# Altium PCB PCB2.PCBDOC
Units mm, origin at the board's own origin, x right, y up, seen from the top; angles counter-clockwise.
Board outline 130.05 x 89.41 mm, 2 copper layers (Top Layer, Bottom Layer); 28 components, 33 nets, 131 pads, 11 vias.
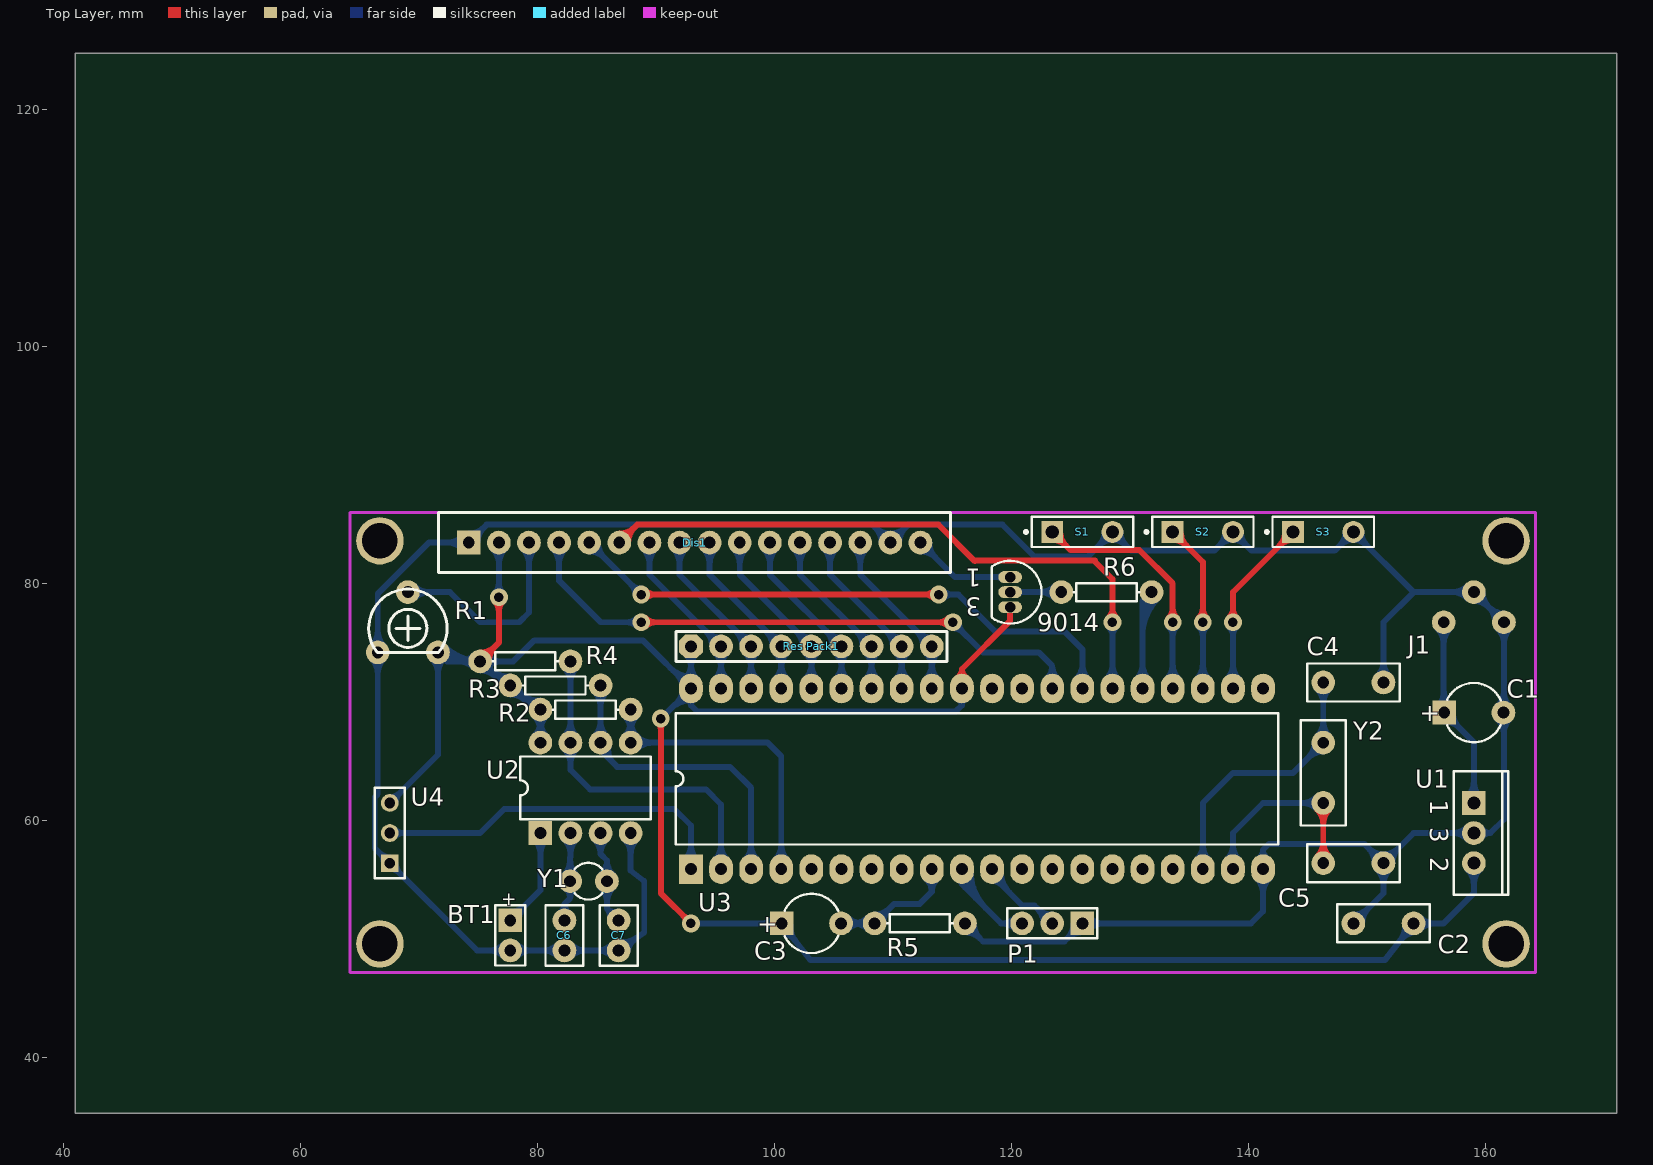
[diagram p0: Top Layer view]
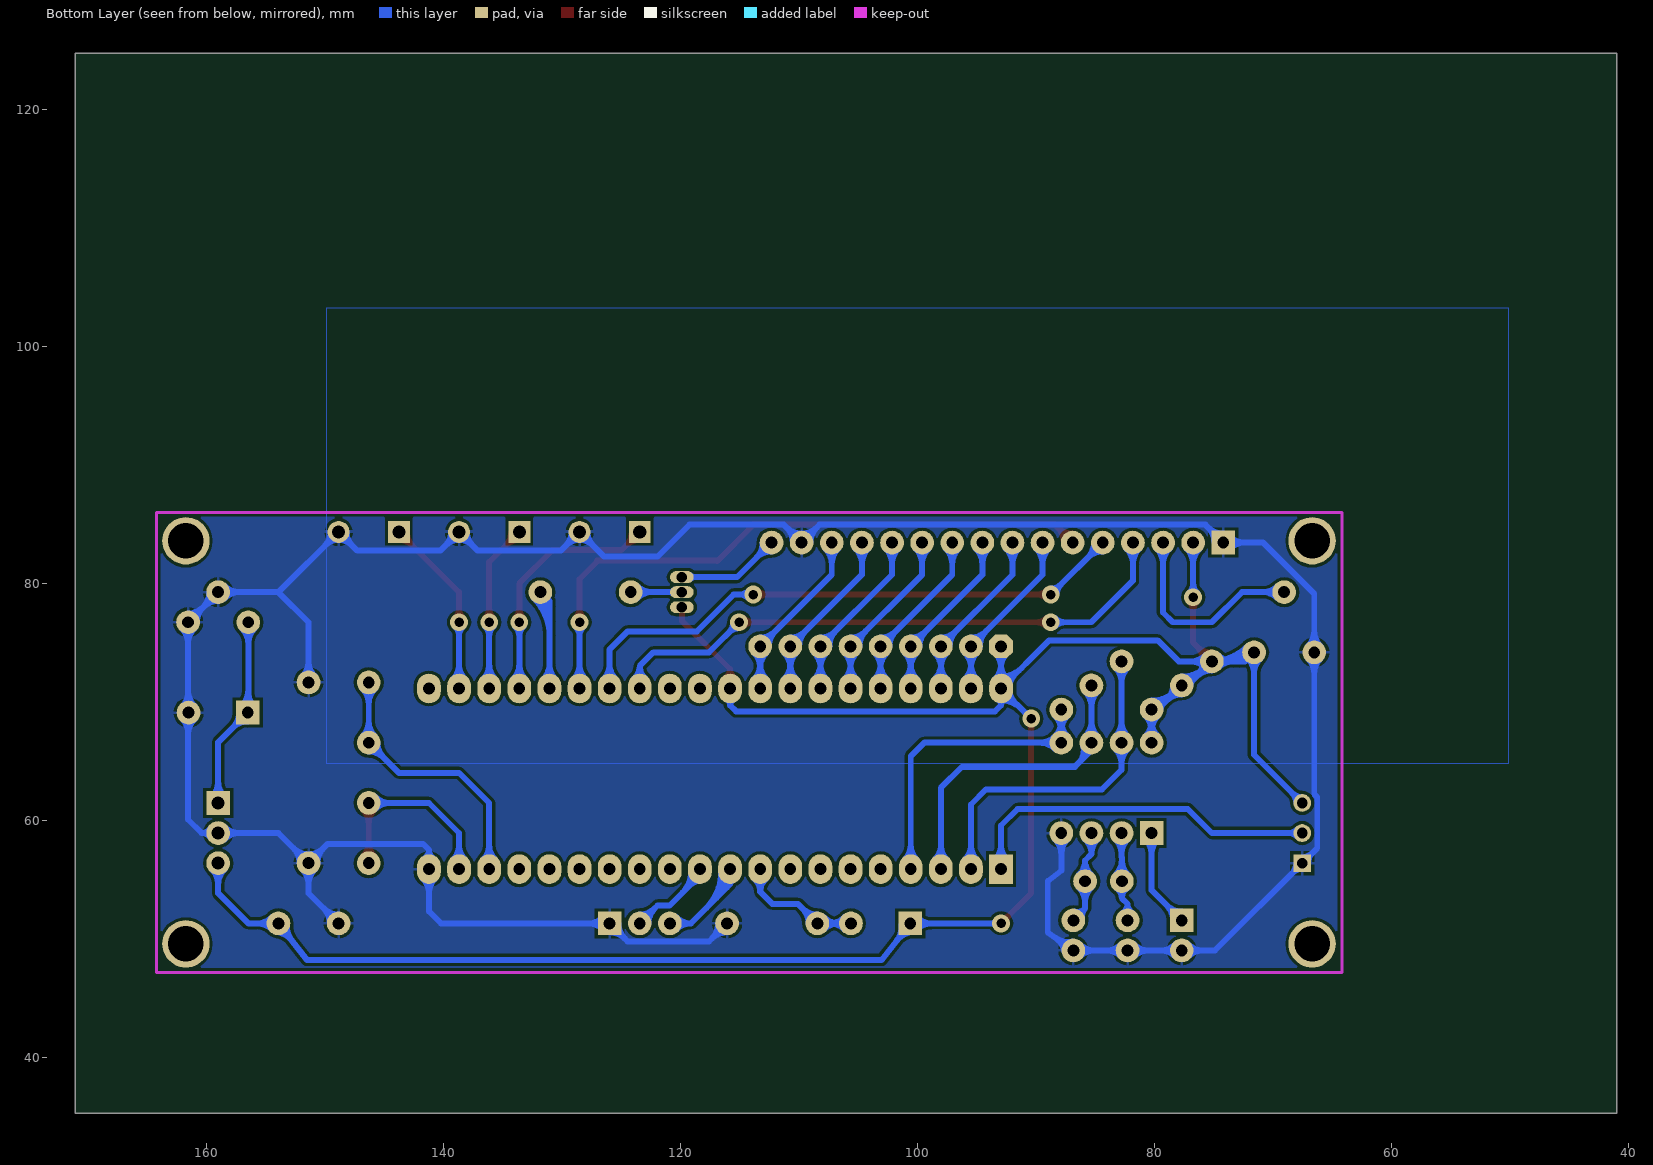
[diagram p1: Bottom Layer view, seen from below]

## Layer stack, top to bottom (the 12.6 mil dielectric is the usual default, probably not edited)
Top Layer: signal copper 0.0356
Dielectric: dielectric 0.32, FR-4, Dk 4.8
Bottom Layer: signal copper 0.0356

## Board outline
41.021,123.063 41.021,35.306 171.069,35.306 171.069,124.714 41.021,124.714

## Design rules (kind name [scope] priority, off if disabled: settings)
Clearance [All] p1: gap=0.254
ComponentClearance [All] p1: gap=0.254 collisioncheckmode=0
PolygonConnect [All] p1: connectstyle=Relief reliefconductorwidth=0.254 reliefentries=4 polygonreliefangle="90 Angle"
RoutingVias [All] p1: holewidth=0.711 width=1.27 viastyle="Through Hole" minholewidth=0.711 minwidth=1.27 maxholewidth=0.711 maxwidth=1.27
SolderMaskExpansion [All] p1: expansion=0.102
TestPointUsage [All] p1: valid=0 allowmultiple=FALSE
Testpoint [All] p1: side=15 testpointundercomponent=TRUE minsize=1.016 maxsize=2.54 preferedsize=1.524 minholesize=0 maxholesize=1.016 preferedholesize=0.813 testpointgrid=0.025 style=1023 order=1234567890
Width [All] p1: maxlimit=0.5 minlimit=0.254 preferedwidth=0.254 toplayer_minwidth=0.5 toplayer_prefwidth=0.5 bottomlayer_minwidth=0.5 bottomlayer_prefwidth=0.5 minimp=50.000000 maximp=50.000000 favimp=50.000000
17 further rules are at their usual default settings.

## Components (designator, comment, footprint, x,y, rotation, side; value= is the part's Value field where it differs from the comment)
9014 "NPN" BCY-W3 119.888,79.248 r180 top (schematic designator Q1)
BT1 "Battery" BAT-2 77.724,50.292 r270 top
C1 "Cap Pol1" CAPPR5-5x5 159.004,69.088 r0 top
C2 "Cap" CAPR5.08-7.8x3.2 151.384,51.308 r0 top
C3 "Cap Pol1" CAPPR5-5x5 103.124,51.308 r0 top
C4 "Cap" CAPR5.08-7.8x3.2 148.844,71.628 r180 top
C5 "Cap" CAPR5.08-7.8x3.2 148.844,56.388 r180 top
C6 "Cap" CAPR2.54-5.1x3.2 82.296,50.292 r90 top
C7 "Cap" CAPR2.54-5.1x3.2 86.868,50.292 r90 top
Dis1 "LCD1602 BIG" 1602 74.224,83.428 r0 top locked
J1 "电源插头" "电源插头 小" 156.464,76.708 r90 top
P1 "Header 3" HDR1X3#1 125.984,51.308 r180 top
R1 "RPot" 蓝白可调 69.088,79.248 r0 top
R2 "Res1" AXIAL-0.3 84.074,69.342 r180 top
R3 "Res1" AXIAL-0.3 81.534,71.374 r180 top
R4 "Res1" AXIAL-0.3 78.994,73.406 r180 top
R5 "Res1" AXIAL-0.3 112.268,51.308 r180 top
R6 "Res1" AXIAL-0.3 128.016,79.248 r180 top
"Res Pack1" "RES Pack" "Res Pack" 92.964,74.676 r90 top locked
S1 "SW-PB" SPST-2 125.984,84.328 r0 top
S2 "SW-PB" SPST-2 136.144,84.328 r0 top
S3 "SW-PB" SPST-2 146.304,84.328 r0 top
U1 "L7805AB-V" TO220ABN 159.004,58.928 r270 top
U2 "DS1302" DIP8 84.074,62.738 r0 top
U3 "STC89C51" DIP40 92.964,55.88 r90 top
U4 "DS18b20" HDR1X3#2 67.564,56.388 r90 top
Y1 "XTAL" BCY-W2/D3.1 84.328,54.864 r270 top
Y2 "XTAL" RAD-0.2 146.304,64.008 r270 top

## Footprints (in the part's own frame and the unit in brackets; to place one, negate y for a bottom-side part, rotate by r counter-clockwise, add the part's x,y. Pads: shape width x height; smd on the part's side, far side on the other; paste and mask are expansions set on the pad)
1602 [mm]
  rect 2x2 hole 1: 1(0,0)
  round 2 hole 1: 2(2.54,0) 3(5.08,0) 4(7.62,0) 5(10.16,0) 6(12.7,0) 7(15.24,0) 8(17.78,0) 9(20.32,0) 10(22.86,0) 11(25.4,0) 12(27.94,0) 13(30.48,0) 14(33.02,0) 15(35.56,0) 16(38.1,0)
  silkscreen extent -2.54,-2.54 40.64,2.54
AXIAL-0.3 [mm] "Resistor; 2 Leads"
  round 2 hole 1: 1(-3.81,0) 2(3.81,0)
  silkscreen extent -2.77,-0.76 2.77,0.76
BAT-2 [mm] "Multicell Battery; 2 Leads"
  rect 2x2 hole 1: 1(-1.27,0)
  round 2 hole 1: 2(1.27,0)
  silkscreen extent -2.54,-1.27 2.54,1.27
BCY-W2/D3.1 [mm] "Crystal, Thru-Hole; 2 Leads; Body 3.1 x 8.2 mm (Dia.xH)"
  round 2 hole 1: 1(0,1.55) 2(0,-1.55)
  silkscreen extent -1.55,-1.19 1.55,1.17
BCY-W3 [mm] "TO, Flat Index; 3 In-Line, Axial Leads; Body Dia. 4.8mm"
  oval 2x1 hole 0.9: 1(0,-1.27) 2(0,0) 3(0,1.27)
  silkscreen extent -2.65,-2.65 1.55,2.65
CAPPR5-5x5 [mm] "Capacitor, Electrolytic, Radial; Body 5 x 5 mm (Dia.xH typ); Pin Spacing 5 mm (typ)"
  rect 2x2 hole 1: 1(-2.5,0)
  round 2 hole 1: 2(2.5,0)
  silkscreen extent -2.26,-2.5 2.27,2.5
CAPR2.54-5.1x3.2 [mm] "Capacitor, Ceramic, Thru-Hole, Dipped Radial; Body 5.1 x 3.2 mm (WxT) Pin Spacing 2.54 mm (typ)"
  round 2 hole 1: 1(-1.27,0) 2(1.27,0)
  silkscreen extent -2.55,-1.6 2.55,1.6
CAPR5.08-7.8x3.2 [mm] "Capacitor, Ceramic, Thru-Hole, Dipped Radial; Body 7.8 x 3.2 mm (WxT) Pin Spacing 5.08 mm (typ)"
  round 2 hole 1: 1(-2.54,0) 2(2.54,0)
  silkscreen extent -3.9,-1.6 3.9,1.6
DIP8 [mm] "DIP; 8 Leads; Row Spacing 7.62 mm; Pitch 2.54 mm"
  rect 2x2 hole 1: 1(-3.81,-3.81)
  round 2 hole 1: 2(-1.27,-3.81) 3(1.27,-3.81) 4(3.81,-3.81) 5(3.81,3.81) 6(1.27,3.81) 7(-1.27,3.81) 8(-3.81,3.81)
  silkscreen extent -5.5,-2.65 5.5,2.65
DIP40 [mm]
  rect 2.5x2 hole 1: 1(0,0)
  oval 2.5x2 hole 1: 2(0,-2.54) 3(0,-5.08) 4(0,-7.62) 5(0,-10.16) 6(0,-12.7) 7(0,-15.24) 8(0,-17.78) 9(0,-20.32) 10(0,-22.86) 11(0,-25.4) 12(0,-27.94) 13(0,-30.48) 14(0,-33.02) 15(0,-35.56) 16(0,-38.1) 17(0,-40.64) 18(0,-43.18) 19(0,-45.72) 20(0,-48.26) 21(15.24,-48.26) 22(15.24,-45.72) 23(15.24,-43.18) 24(15.24,-40.64) 25(15.24,-38.1) 26(15.24,-35.56) 27(15.24,-33.02) 28(15.24,-30.48) 29(15.24,-27.94) 30(15.24,-25.4) 31(15.24,-22.86) 32(15.24,-20.32) 33(15.24,-17.78) 34(15.24,-15.24) 35(15.24,-12.7) 36(15.24,-10.16) 37(15.24,-7.62) 38(15.24,-5.08) 39(15.24,-2.54) 40(15.24,0)
  silkscreen extent 2.08,-49.53 13.16,1.27
HDR1X3#1 [mm] "Connector; Header; 3 Position"
  rect 2x2 hole 1: 1(0,0)
  round 2 hole 1: 2(2.54,0) 3(5.08,0)
  silkscreen extent -1.27,-1.27 6.35,1.27
HDR1X3#2 [mm] "Connector; Header; 3 Position"
  rect 1.5x1.5 hole 0.9: 1(0,0)
  round 1.5 hole 0.9: 2(2.54,0) 3(5.08,0)
  silkscreen extent -1.27,-1.27 6.35,1.27
RAD-0.2 [mm] "Jumper Wire; 2 Leads"
  round 2 hole 1: 1(-2.54,0) 2(2.54,0)
  silkscreen extent -4.44,-1.91 4.44,1.91
"Res Pack" [mm]
  oct 2x2 hole 1: 1(0,0)
  round 2 hole 1: 2(0,-2.54) 3(0,-5.08) 4(0,-7.62) 5(0,-10.16) 6(0,-12.7) 7(0,-15.24) 8(0,-17.78) 9(0,-20.32)
  silkscreen extent -1.27,-21.59 1.27,1.27
SPST-2 [mm] "Circuit Breaker; 2 Leads"
  rect 1.85x1.85 hole 1.1: 1(-2.54,0)
  round 1.85 hole 1.1: 2(2.54,0)
  silkscreen extent -4.89,-1.27 4.28,1.27
TO220ABN [mm] "TO, Thru-Hole, Vertical, Heatsink Mounted; 3 In-Line Leads; Pitch 2.54 mm; Pin sequence 1, 3, 2"
  rect 2x2 hole 1.1: 1(-2.54,0)
  round 2 hole 1.1: 2(2.54,0) 3(0,0)
  silkscreen extent -5.2,-1.7 5.2,2.9
"电源插头 小" [mm]
  round 2 hole 1: 1(0,0) 2(0,-5.08) 3(2.54,-2.54)
蓝白可调 [mm]
  round 2 hole 1: 1(0,0) 2(-2.54,-5.08) 3(2.54,-5.08)
  silkscreen extent -3.3,-5.11 3.3,0.25

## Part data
9014: "NPN Bipolar Transistor"
BT1: "Multicell Battery"
C1 C3: "Polarized Capacitor (Radial)"
C2 C4 C5 C6 C7: "Capacitor"
P1: "Header, 3-Pin"
R1: "Potentiometer"
R2 R3 R4 R5 R6: "Resistor"
S1 S2 S3: "Switch"
U1: "Precision 1A Regulator"
Y1 Y2: "Crystal Oscillator"

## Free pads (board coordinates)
  round 4 hole 3: 0(66.724,83.579) 1(66.724,49.579) 1(161.724,83.579) 2(161.724,49.579)

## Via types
v1: diameter 1.5, hole 0.8, Top Layer to Bottom Layer, 11 vias

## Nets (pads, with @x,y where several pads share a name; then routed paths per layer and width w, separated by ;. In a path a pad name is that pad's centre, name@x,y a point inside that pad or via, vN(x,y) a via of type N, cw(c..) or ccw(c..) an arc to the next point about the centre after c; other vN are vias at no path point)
GND: BT1.2 C1.2 C2.1 C4.1 C5.1 C6.1 C7.1 Dis1.1 Dis1.15 J1.2 J1.3 P1.1 R1.2 R5.1 S1.2 S2.2 S3.2 U1.3 U2.4 U3.20 U4.1 | length 355.1
  Bottom Layer w0.5: R1.2@66.018,73.638 cw(c64.737,72.357) 66.548,72.357 cw(c68.359,72.357) R1.2@67.078,73.638 ; R1.2@66.018,74.698 ccw(c64.737,75.979) 66.548,75.979 ccw(c68.359,75.979) R1.2@67.078,74.698 ; U4.1@67.064,56.388 ccw(c65.857,56.388) 66.71,57.242 ccw(c67.564,58.095) U4.1@67.564,56.888 ; U4.1@67.564,55.888 cw(c67.564,54.681) 68.418,55.534 cw(c69.271,56.388) U4.1@68.064,56.388 ; Dis1.1@73.694,82.898 ccw(c72.413,81.617) 72.413,83.428 ccw(c72.413,85.239) Dis1.1@73.694,83.958 ; Dis1.1@74.224,84.178 ccw(c74.224,85.989) 75.504,84.708 ccw(c76.785,83.428) Dis1.1@74.974,83.428 ; BT1.2@77.194,48.492 ccw(c75.913,47.211) 75.913,49.022 ccw(c75.913,50.833) BT1.2@77.194,49.552 ; BT1.2@78.254,48.492 cw(c79.535,47.211) 79.535,49.022 cw(c79.535,50.833) BT1.2@78.254,49.552 ; C6.1@81.766,48.492 ccw(c80.485,47.211) 80.485,49.022 ccw(c80.485,50.833) C6.1@81.766,49.552 ; C6.1@82.826,48.492 cw(c84.107,47.211) 84.107,49.022 cw(c84.107,50.833) C6.1@82.826,49.552 ; C7.1@86.338,48.492 ccw(c85.057,47.211) 85.057,49.022 ccw(c85.057,50.833) C7.1@86.338,49.552 ; C7.1@86.995,49.761 ccw(c87.303,51.545) 88.347,50.066 ccw(c89.391,48.587) C7.1@87.607,48.895 ; U2.4@87.354,58.398 cw(c86.073,57.117) 87.884,57.117 cw(c89.695,57.117) U2.4@88.414,58.398 ; U2.4 87.884,55.753 89.027,54.864 89.027,50.546 C7.1 C6.1 BT1.2 74.93,49.022 U4.1 66.294,57.658 66.294,61.951 66.548,62.205 66.548,79.121 70.855,83.428 Dis1.1 75.734,84.938 108.274,84.938 Dis1.15 111.294,84.938 119.253,84.938 121.945,82.245 126.441,82.245 S1.2 130.099,82.753 137.109,82.753 S2.2 140.259,82.753 147.269,82.753 S3.2 153.924,79.248 ; Dis1.15@109.034,83.428 ccw(c107.223,83.428) 108.504,84.708 ccw(c109.784,85.989) 109.784,84.178 ccw(c109.784,85.989) 111.064,84.708 ccw(c112.345,83.428) Dis1.15@110.534,83.428 ; R5.1@116.078,50.558 cw(c116.078,48.747) 117.358,50.028 cw(c118.639,51.308) R5.1@116.828,51.308 ; R5.1 117.602,49.784 124.46,49.784 P1.1 140.208,51.308 141.224,52.324 U3.20 141.224,57.506 ; P1.1@125.234,51.308 cw(c123.423,51.308) 124.704,50.028 cw(c125.984,48.747) P1.1@125.984,50.558 ; P1.1@126.514,50.778 cw(c127.795,49.497) 127.795,51.308 cw(c127.795,53.119) P1.1@126.514,51.838 ; S1.2@127.849,84.328 cw(c126.219,84.328) 127.372,83.176 cw(c128.524,82.023) 128.524,83.653 cw(c128.524,82.023) 129.676,83.176 cw(c130.829,84.328) S1.2@129.199,84.328 ; S2.2@138.009,84.328 cw(c136.379,84.328) 137.532,83.176 cw(c138.684,82.023) 138.684,83.653 cw(c138.684,82.023) 139.836,83.176 cw(c140.989,84.328) S2.2@139.359,84.328 ; U3.20@140.694,55.1 cw(c139.413,53.819) 141.224,53.819 cw(c143.035,53.819) U3.20@141.754,55.1 ; U3.20@140.818,56.76 ccw(c140.338,57.506) 141.224,57.506 ; U3.20@141.63,56.76 cw(c142.11,57.506) 141.224,57.506 ; S3.2@148.169,84.328 cw(c146.539,84.328) 147.692,83.176 cw(c148.844,82.023) 148.844,83.653 cw(c148.844,82.023) 149.996,83.176 cw(c151.149,84.328) S3.2@149.519,84.328 ; C2.1 151.384,53.848 C5.1 ; C2.1@148.844,52.058 ccw(c148.844,53.869) 150.124,52.588 ccw(c151.405,51.308) C2.1@149.594,51.308 ; C5.1@150.634,56.388 ccw(c148.823,56.388) 150.104,57.668 ccw(c151.384,58.949) 151.384,57.138 ccw(c151.384,58.949) 152.664,57.668 ccw(c153.945,56.388) C5.1@152.134,56.388 ; C5.1@150.854,55.858 cw(c149.573,54.577) 151.384,54.577 cw(c153.195,54.577) C5.1@151.914,55.858 ; C4.1@150.854,72.158 ccw(c149.573,73.439) 151.384,73.439 ccw(c153.195,73.439) C4.1@151.914,72.158 ; C4.1 151.384,76.708 153.924,79.248 ; U1.3@158.474,58.398 ccw(c157.193,57.117) 157.193,58.928 ccw(c157.193,60.739) U1.3@158.474,59.458 ; J1.3@158.474,78.718 ccw(c157.193,77.437) 157.193,79.248 ccw(c157.193,81.059) J1.3@158.474,79.778 ; J1.3@159.004,78.498 cw(c159.004,76.687) 160.284,77.968 cw(c161.565,79.248) J1.3@159.754,79.248 ; U1.3@159.629,58.514 cw(c160.401,58.002) 160.401,58.928 ; U1.3@159.629,59.342 ccw(c160.401,59.854) 160.401,58.928 ; J1.2@160.794,76.708 ccw(c158.983,76.708) 160.264,77.988 ccw(c161.544,79.269) J1.2@161.544,77.458 ; C1.2@160.974,68.558 cw(c159.597,67.181) 161.544,67.181 ; C1.2@160.974,69.618 ccw(c159.597,70.995) 161.544,70.995 ; J1.2@161.014,76.178 cw(c159.733,74.897) 161.544,74.897 cw(c163.355,74.897) J1.2@162.074,76.178 ; 161.544,67.374 cw(c163.218,67.374) C1.2@162.034,68.558 ; 161.544,70.802 ccw(c163.218,70.802) C1.2@162.034,69.618 ; 141.224,57.506 141.732,58.014 149.758,58.014 C5.1 ; C5.1 153.924,58.928 U1.3 160.401,58.928 ; 153.924,79.248 J1.3 J1.2 161.544,69.088 161.544,60.071 160.401,58.928
LEDA: R6.1 U3.25 | length 19.8
  Bottom Layer w0.5: U3.25@130.534,71.9 ccw(c129.253,73.181) 131.064,73.181 ccw(c132.875,73.181) U3.25@131.594,71.9 ; U3.25 131.064,78.486 ; 131.064,75.598 cw(c135.476,75.598) R6.1@132.356,78.718 ; 131.064,76.805 cw(c134.269,76.805) R6.1@132.003,79.071 ; 131.064,78.012 cw(c133.062,78.012) R6.1@131.649,79.425 ; R6.1@131.144,78.935 cw(c130.782,78.768) 131.064,78.486 ; R6.1@131.513,78.566 ccw(c131.346,78.204) 131.064,78.486 ; R6.1 131.064,78.486
NetBT1_1: BT1.1 U2.1 | length 14.1
  Bottom Layer w0.5: BT1.1 80.264,54.102 U2.1 ; BT1.1@77.724,52.312 ccw(c77.724,54.123) 79.004,52.842 ccw(c80.285,51.562) BT1.1@78.474,51.562 ; U2.1@79.734,58.398 cw(c78.453,57.117) 80.264,57.117 cw(c82.075,57.117) U2.1@80.794,58.398
NetC1_1: C1.1 J1.1 U1.1 | length 27.7
  Bottom Layer w0.5: J1.1@155.934,76.178 cw(c154.653,74.897) 156.464,74.897 cw(c158.275,74.897) J1.1@156.994,76.178 ; C1.1@155.974,69.618 ccw(c154.79,70.802) 156.464,70.802 ; 156.464,70.995 ccw(c158.411,70.995) C1.1@157.034,69.618 ; J1.1 156.464,69.128 C1.1 159.004,66.588 U1.1 ; C1.1@156.504,68.338 cw(c156.504,66.527) 157.784,67.808 cw(c159.065,69.088) C1.1@157.254,69.088 ; U1.1@158.474,61.998 ccw(c157.193,63.279) 159.004,63.279 ccw(c160.815,63.279) U1.1@159.534,61.998
NetC3_2: C3.2 R5.2 U3.9 | length 21.7
  Bottom Layer w0.5: C3.2 R5.2 110.109,52.959 112.268,52.959 113.284,53.975 ; C3.2@106.154,50.778 cw(c107.435,49.497) 107.435,51.308 cw(c107.435,53.119) C3.2@106.154,51.838 ; R5.2@107.928,50.778 ccw(c106.647,49.497) 106.647,51.308 ccw(c106.647,53.119) R5.2@107.928,51.838 ; R5.2@108.458,52.058 ccw(c108.458,53.869) 109.738,52.588 ccw(c111.019,51.308) R5.2@109.208,51.308 ; U3.9@112.79,55.066 cw(c111.833,53.975) 113.284,53.975 ; U3.9 113.284,53.975 ; U3.9@113.778,55.066 ccw(c114.735,53.975) 113.284,53.975
NetC4_2: C4.2 U3.18 Y2.1 | length 34.3
  Bottom Layer w0.5: U3.18@135.614,56.66 ccw(c134.333,57.941) 136.144,57.941 ccw(c137.955,57.941) U3.18@136.674,56.66 ; U3.18 136.144,61.468 138.684,64.008 143.764,64.008 Y2.1 C4.2 ; Y2.1@145.554,66.548 cw(c143.743,66.548) 145.024,65.268 cw(c146.304,63.987) Y2.1@146.304,65.798 ; Y2.1@145.774,67.078 ccw(c144.493,68.359) 146.304,68.359 ccw(c148.115,68.359) Y2.1@146.834,67.078 ; C4.2@145.774,71.098 cw(c144.493,69.817) 146.304,69.817 cw(c148.115,69.817) C4.2@146.834,71.098
NetC5_2: C5.2 U3.19 Y2.2 | length 28.2
  Top Layer w0.5: C5.2@145.774,56.918 ccw(c144.493,58.199) 146.304,58.199 ccw(c148.115,58.199) C5.2@146.834,56.918 ; Y2.2@145.774,60.938 cw(c144.493,59.657) 146.304,59.657 cw(c148.115,59.657) Y2.2@146.834,60.938 ; C5.2 Y2.2
  Bottom Layer w0.5: U3.19@138.154,56.66 ccw(c136.873,57.941) 138.684,57.941 ccw(c140.495,57.941) U3.19@139.214,56.66 ; U3.19 138.684,58.928 141.224,61.468 Y2.2 ; Y2.2@145.774,60.938 ccw(c144.493,59.657) 144.493,61.468 ccw(c144.493,63.279) Y2.2@145.774,61.998
NetC6_2: C6.2 U2.2 Y1.2 | length 16.9
  Bottom Layer w0.5: C6.2@81.882,52.187 ccw(c81.37,52.959) 82.296,52.959 ; Y1.2@82.248,55.394 ccw(c80.967,56.675) 82.778,56.675 ccw(c84.589,56.675) Y1.2@83.308,55.394 ; U2.2@82.274,58.398 cw(c80.993,57.117) 82.804,57.117 cw(c84.615,57.117) U2.2@83.334,58.398 ; C6.2 82.296,52.959 ; Y1.2@82.354,54.245 cw(c81.803,53.441) 82.778,53.441 ; C6.2@82.71,52.187 cw(c83.222,52.959) 82.296,52.959 ; 82.778,56.871 Y1.2 82.778,53.441 ; 82.804,56.897 U2.2 ; Y1.2@83.202,54.245 ccw(c83.753,53.441) 82.778,53.441 ; 82.296,52.959 82.778,53.441
NetC7_2: C7.2 U2.3 Y1.1 | length 18.1
  Bottom Layer w0.5: U2.3@84.821,58.391 cw(c83.613,57.151) 85.344,57.151 cw(c87.075,57.151) U2.3@85.867,58.391 ; U2.3 85.344,57.151 85.878,56.617 ; Y1.1@85.348,54.334 cw(c84.067,53.053) 85.878,53.053 cw(c87.689,53.053) Y1.1@86.408,54.334 ; Y1.1@85.36,55.407 ccw(c84.205,56.617) 85.878,56.617 ; C7.2@86.133,51.71 ccw(c85.219,51.893) 85.878,52.552 ccw(c86.537,53.211) C7.2@86.72,52.297 ; Y1.1@86.396,55.407 cw(c87.551,56.617) 85.878,56.617 ; C7.2 85.878,52.552 Y1.1 85.878,56.617
NetDis1_4: Dis1.4 U3.28 | length 62.5
  Top Layer w0.5: v1(88.773,76.708) v1@114.935,76.708 ; v1@89.127,76.354 cw(c89.98,75.501) 89.98,76.708 cw(c89.98,77.915) v1@89.127,77.062 ; v1@114.708,76.354 ccw(c113.855,75.501) 113.855,76.708 ccw(c113.855,77.915) v1@114.708,77.062
  Bottom Layer w0.5: Dis1.4@81.314,82.898 cw(c80.033,81.617) 81.844,81.617 cw(c83.655,81.617) Dis1.4@82.374,82.898 ; Dis1.4 81.844,80.208 85.344,76.708 v1(88.773,76.708) ; v1@88.419,76.354 ccw(c87.566,75.501) 87.566,76.708 ccw(c87.566,77.915) v1@88.419,77.062 ; v1@115.062,76.208 cw(c115.062,75.001) 115.916,75.854 cw(c116.769,76.708) v1@115.562,76.708 ; v1(115.062,76.708) 117.602,74.168 122.301,74.168 123.444,73.025 ; U3.28@122.95,71.934 ccw(c121.993,73.025) 123.444,73.025 ; U3.28 123.444,73.025 ; U3.28@123.938,71.934 cw(c124.895,73.025) 123.444,73.025
NetDis1_5: Dis1.5 U3.27 | length 61.9
  Top Layer w0.5: v1(88.767,79.045) v1(113.868,79.045) ; v1@89.121,78.691 cw(c89.974,77.838) 89.974,79.045 cw(c89.974,80.252) v1@89.121,79.398 ; v1@113.515,78.691 ccw(c112.661,77.838) 112.661,79.045 ccw(c112.661,80.252) v1@113.515,79.398
  Bottom Layer w0.5: Dis1.5@84.384,82.678 cw(c84.384,80.867) 85.664,82.148 cw(c86.945,83.428) Dis1.5@85.134,83.428 ; Dis1.5 v1(88.767,79.045) ; v1@88.267,79.045 ccw(c87.06,79.045) 87.914,79.898 ccw(c88.767,80.752) v1@88.767,79.545 ; v1(113.868,79.045) 115.519,79.045 118.618,75.946 124.46,75.946 125.984,74.422 U3.27 ; v1@114.222,78.691 cw(c115.075,77.838) 115.075,79.045 cw(c115.075,80.252) v1@114.222,79.398 ; U3.27@125.454,71.9 ccw(c124.173,73.181) 125.984,73.181 ccw(c127.795,73.181) U3.27@126.514,71.9
NetDis1_6: Dis1.6 U3.26 | length 62.8
  Top Layer w0.5: Dis1.6 88.434,84.938 113.843,84.938 116.916,81.864 ; Dis1.6@86.924,84.178 ccw(c86.924,85.989) 88.204,84.708 ccw(c89.485,83.428) Dis1.6@87.674,83.428 ; 116.967,81.915 127.051,81.915 ; 127,81.864 128.524,80.34 v1(128.524,76.708) ; v1@128.17,77.062 ccw(c127.317,77.915) 128.524,77.915 ccw(c129.731,77.915) v1@128.878,77.062
  Bottom Layer w0.5: U3.26@127.994,71.9 ccw(c126.713,73.181) 128.524,73.181 ccw(c130.335,73.181) U3.26@129.054,71.9 ; v1@128.17,76.354 cw(c127.317,75.501) 128.524,75.501 cw(c129.731,75.501) v1@128.878,76.354 ; U3.26 v1(128.524,76.708)
NetDis1_7: "Res Pack1.2" Dis1.7 U3.39 | length 26.2
  Bottom Layer w0.5: Dis1.7@88.934,82.898 cw(c87.653,81.617) 89.464,81.617 cw(c91.275,81.617) Dis1.7@89.994,82.898 ; Dis1.7 89.464,80.716 95.504,74.676 U3.39 ; 94.754,74.676 ccw(c92.943,74.676) 94.224,75.956 ccw(c95.504,77.237) 95.504,75.426 ; U3.39@94.974,71.9 ccw(c93.693,73.181) 95.504,73.181 ccw(c97.315,73.181) U3.39@96.034,71.9 ; 94.974,74.146 cw(c93.693,72.865) 95.504,72.865 cw(c97.315,72.865) 96.034,74.146
NetDis1_8: "Res Pack1.3" Dis1.8 U3.38 | length 26.2
  Bottom Layer w0.5: Dis1.8@91.474,82.898 cw(c90.193,81.617) 92.004,81.617 cw(c93.815,81.617) Dis1.8@92.534,82.898 ; Dis1.8 92.004,80.716 98.044,74.676 U3.38 ; 97.294,74.676 ccw(c95.483,74.676) 96.764,75.956 ccw(c98.044,77.237) 98.044,75.426 ; U3.38@97.514,71.9 ccw(c96.233,73.181) 98.044,73.181 ccw(c99.855,73.181) U3.38@98.574,71.9 ; 97.514,74.146 cw(c96.233,72.865) 98.044,72.865 cw(c99.855,72.865) 98.574,74.146
NetDis1_9: "Res Pack1.4" Dis1.9 U3.37 | length 26.2
  Bottom Layer w0.5: Dis1.9@94.014,82.898 cw(c92.733,81.617) 94.544,81.617 cw(c96.355,81.617) Dis1.9@95.074,82.898 ; Dis1.9 94.544,80.716 100.584,74.676 U3.37 ; 99.834,74.676 ccw(c98.023,74.676) 99.304,75.956 ccw(c100.584,77.237) 100.584,75.426 ; U3.37@100.054,71.9 ccw(c98.773,73.181) 100.584,73.181 ccw(c102.395,73.181) U3.37@101.114,71.9 ; 100.054,74.146 cw(c98.773,72.865) 100.584,72.865 cw(c102.395,72.865) 101.114,74.146
NetDis1_10: "Res Pack1.5" Dis1.10 U3.36 | length 26.2
  Bottom Layer w0.5: Dis1.10@96.554,82.898 cw(c95.273,81.617) 97.084,81.617 cw(c98.895,81.617) Dis1.10@97.614,82.898 ; Dis1.10 97.084,80.716 103.124,74.676 U3.36 ; 102.374,74.676 ccw(c100.563,74.676) 101.844,75.956 ccw(c103.124,77.237) 103.124,75.426 ; U3.36@102.594,71.9 ccw(c101.313,73.181) 103.124,73.181 ccw(c104.935,73.181) U3.36@103.654,71.9 ; 102.594,74.146 cw(c101.313,72.865) 103.124,72.865 cw(c104.935,72.865) 103.654,74.146
NetDis1_11: "Res Pack1.6" Dis1.11 U3.35 | length 26.2
  Bottom Layer w0.5: Dis1.11@99.094,82.898 cw(c97.813,81.617) 99.624,81.617 cw(c101.435,81.617) Dis1.11@100.154,82.898 ; Dis1.11 99.624,80.716 105.664,74.676 U3.35 ; 104.914,74.676 ccw(c103.103,74.676) 104.384,75.956 ccw(c105.664,77.237) 105.664,75.426 ; U3.35@105.134,71.9 ccw(c103.853,73.181) 105.664,73.181 ccw(c107.475,73.181) U3.35@106.194,71.9 ; 105.134,74.146 cw(c103.853,72.865) 105.664,72.865 cw(c107.475,72.865) 106.194,74.146
NetDis1_12: "Res Pack1.7" Dis1.12 U3.34 | length 26.2
  Bottom Layer w0.5: Dis1.12@101.634,82.898 cw(c100.353,81.617) 102.164,81.617 cw(c103.975,81.617) Dis1.12@102.694,82.898 ; Dis1.12 102.164,80.716 108.204,74.676 U3.34 ; 107.454,74.676 ccw(c105.643,74.676) 106.924,75.956 ccw(c108.204,77.237) 108.204,75.426 ; U3.34@107.674,71.9 ccw(c106.393,73.181) 108.204,73.181 ccw(c110.015,73.181) U3.34@108.734,71.9 ; 107.674,74.146 cw(c106.393,72.865) 108.204,72.865 cw(c110.015,72.865) 108.734,74.146
NetDis1_13: "Res Pack1.8" Dis1.13 U3.33 | length 26.2
  Bottom Layer w0.5: Dis1.13@104.174,82.898 cw(c102.893,81.617) 104.704,81.617 cw(c106.515,81.617) Dis1.13@105.234,82.898 ; Dis1.13 104.704,80.716 110.744,74.676 U3.33 ; 109.994,74.676 ccw(c108.183,74.676) 109.464,75.956 ccw(c110.744,77.237) 110.744,75.426 ; U3.33@110.214,71.9 ccw(c108.933,73.181) 110.744,73.181 ccw(c112.555,73.181) U3.33@111.274,71.9 ; 110.214,74.146 cw(c108.933,72.865) 110.744,72.865 cw(c112.555,72.865) 111.274,74.146
NetDis1_14: "Res Pack1.9" Dis1.14 U3.32 | length 26.2
  Bottom Layer w0.5: Dis1.14@106.714,82.898 cw(c105.433,81.617) 107.244,81.617 cw(c109.055,81.617) Dis1.14@107.774,82.898 ; Dis1.14 107.244,80.716 113.284,74.676 U3.32 ; 112.534,74.676 ccw(c110.723,74.676) 112.004,75.956 ccw(c113.284,77.237) 113.284,75.426 ; U3.32@112.754,71.9 ccw(c111.473,73.181) 113.284,73.181 ccw(c115.095,73.181) U3.32@113.814,71.9 ; 112.754,74.146 cw(c111.473,72.865) 113.284,72.865 cw(c115.095,72.865) 113.814,74.146
NetDis1_16: 9014.1 Dis1.16 | length 12.6
  Bottom Layer w0.5: Dis1.16@112.324,82.678 cw(c112.324,80.867) 113.604,82.148 cw(c114.885,83.428) Dis1.16@113.074,83.428 ; Dis1.16 115.234,80.518 9014.1 ; 9014.1@119.211,80.341 ccw(c118.784,79.914) 118.784,80.518 ccw(c118.784,81.122) 9014.1@119.211,80.695
NetP1_2: P1.2 U3.11 | length 13.9
  Bottom Layer w0.5: U3.11@118.364,54.88 cw(c118.364,53.692) 119.204,54.532 ; U3.11 118.364,55.372 120.924,52.812 121.94,52.812 P1.2 ; U3.11@118.614,55.63 ccw(c119.84,55.63) 118.973,54.763 ; U3.11@119.114,55.63 ccw(c121.548,55.63) 119.827,53.909 ; P1.2@122.694,51.308 ccw(c120.883,51.308) 122.164,52.588 ccw(c123.444,53.869) P1.2@123.444,52.058
NetP1_3: P1.3 U3.10 | length 19.3
  Bottom Layer w0.5: U3.10@115.574,55.63 ccw(c117.433,55.63) 116.118,54.316 ; U3.10 115.824,54.61 ; U3.10@116.074,55.63 ccw(c119.14,55.63) 116.972,53.462 ; U3.10@116.574,55.63 ccw(c120.847,55.63) 117.826,52.608 ; P1.3@120.367,50.785 ccw(c119.126,49.576) 119.126,51.308 ; P1.3@120.367,51.831 cw(c119.126,53.04) 119.126,51.308 ; P1.3 119.126,51.308 ; 115.824,54.61 ccw(c115.505,54.61) 115.6,54.914 cw(c115.505,54.61) 115.824,54.61 ; 115.824,54.61 cw(c116.143,54.61) 116.048,54.914 ccw(c116.143,54.61) 115.824,54.61 ; 115.824,54.61 119.126,51.308
NetQ1_2: 9014.2 R6.2 | length 7.6
  Bottom Layer w0.5: 9014.2 R6.2@123.698,79.248 ; 9014.2@120.565,79.071 cw(c120.992,78.644) 120.992,79.248 cw(c120.992,79.852) 9014.2@120.565,79.425 ; R6.2@123.676,78.718 ccw(c122.395,77.437) 122.395,79.248 ccw(c122.395,81.059) R6.2@123.676,79.778
NetR2_1: R2.1 U2.5 U3.4 | length 36.9
  Bottom Layer w0.5: U2.5@87.354,67.078 ccw(c86.073,68.359) 87.884,68.359 ccw(c89.695,68.359) 88.414,67.078 ccw(c89.695,68.359) 89.695,66.548 ccw(c89.695,64.737) U2.5@88.414,66.018 ; R2.1@87.354,68.812 cw(c86.073,67.531) 87.884,67.531 cw(c89.695,67.531) R2.1@88.414,68.812 ; R2.1 U2.5 99.441,66.548 100.584,65.405 U3.4 ; U3.4@100.054,56.66 ccw(c98.773,57.941) 100.584,57.941 ccw(c102.395,57.941) U3.4@101.114,56.66
NetR3_1: R3.1 U2.6 U3.3 | length 37.6
  Bottom Layer w0.5: U2.6@84.814,67.078 ccw(c83.533,68.359) 85.344,68.359 ccw(c87.155,68.359) U2.6@85.874,67.078 ; R3.1@84.814,70.844 cw(c83.533,69.563) 85.344,69.563 cw(c87.155,69.563) R3.1@85.874,70.844 ; R3.1 U2.6 85.344,65.913 86.741,64.516 96.266,64.516 98.044,62.738 U3.3 ; U2.6@85.582,66.473 ccw(c86.582,66.157) 85.841,65.416 ; U2.6@86.059,66.322 ccw(c87.468,65.878) 86.423,64.834 ; U3.3@97.514,56.66 ccw(c96.233,57.941) 98.044,57.941 ccw(c99.855,57.941) U3.3@98.574,56.66
NetR4_1: R4.1 U2.7 U3.2 | length 39.9
  Bottom Layer w0.5: U2.7@82.274,66.018 cw(c80.993,64.737) 82.804,64.737 cw(c84.615,64.737) U2.7@83.334,66.018 ; U2.7@82.274,67.078 ccw(c80.993,68.359) 82.804,68.359 ccw(c84.615,68.359) U2.7@83.334,67.078 ; R4.1@82.274,72.876 cw(c80.993,71.595) 82.804,71.595 cw(c84.615,71.595) R4.1@83.334,72.876 ; R4.1 U2.7 82.804,64.262 84.455,62.611 94.234,62.611 95.504,61.341 U3.2 ; U3.2@94.974,56.66 ccw(c93.693,57.941) 95.504,57.941 ccw(c97.315,57.941) U3.2@96.034,56.66
NetS1_1: S1.1 U3.24 | length 30
  Top Layer w0.5: S1.1@123.444,83.653 cw(c123.444,82.023) 124.596,83.176 cw(c125.749,84.328) S1.1@124.119,84.328 ; S1.1 124.968,82.804 130.785,82.804 133.604,79.985 v1(133.604,76.708) ; v1@133.25,77.062 ccw(c132.397,77.915) 133.604,77.915 ccw(c134.811,77.915) v1@133.958,77.062
  Bottom Layer w0.5: U3.24@133.074,71.9 ccw(c131.793,73.181) 133.604,73.181 ccw(c135.415,73.181) U3.24@134.134,71.9 ; v1@133.25,76.354 cw(c132.397,75.501) 133.604,75.501 cw(c134.811,75.501) v1@133.958,76.354 ; U3.24 v1(133.604,76.708)
NetS2_1: S2.1 U3.23 | length 23.5
  Top Layer w0.5: S2.1@133.604,83.653 cw(c133.604,82.023) 134.756,83.176 cw(c135.909,84.328) S2.1@134.279,84.328 ; S2.1 136.144,81.788 v1(136.144,76.708) ; v1@135.79,77.062 ccw(c134.937,77.915) 136.144,77.915 ccw(c137.351,77.915) v1@136.498,77.062
  Bottom Layer w0.5: U3.23@135.614,71.9 ccw(c134.333,73.181) 136.144,73.181 ccw(c137.955,73.181) U3.23@136.674,71.9 ; v1@135.79,76.354 cw(c134.937,75.501) 136.144,75.501 cw(c137.351,75.501) v1@136.498,76.354 ; U3.23 v1(136.144,76.708)
NetS3_1: S3.1 U3.22 | length 24.5
  Top Layer w0.5: v1@138.33,77.062 ccw(c137.477,77.915) 138.684,77.915 ccw(c139.891,77.915) v1@139.038,77.062 ; v1(138.684,76.708) 138.684,79.248 S3.1 ; S3.1@143.089,84.328 cw(c141.459,84.328) 142.612,83.176 cw(c143.764,82.023) S3.1@143.764,83.653
  Bottom Layer w0.5: U3.22@138.154,71.9 ccw(c136.873,73.181) 138.684,73.181 ccw(c140.495,73.181) U3.22@139.214,71.9 ; v1@138.33,76.354 cw(c137.477,75.501) 138.684,75.501 cw(c139.891,75.501) v1@139.038,76.354 ; U3.22 v1(138.684,76.708)
NetU3_4: U3.1 U4.2 | length 34.9
  Bottom Layer w0.5: U4.2 75.184,58.928 77.216,60.96 91.567,60.96 92.964,59.563 U3.1@92.964,56.261 ; U4.2@67.918,58.574 cw(c68.771,57.721) 68.771,58.928 cw(c68.771,60.135) U4.2@67.918,59.282 ; U3.1@92.434,56.66 ccw(c91.153,57.941) 92.964,57.941 ccw(c94.775,57.941) U3.1@93.494,56.66
VCC: 9014.3 "Res Pack1.1" C2.2 C3.1 Dis1.2 R1.3 R2.2 R3.2 R4.2 U1.2 U2.8 U3.31 U3.40 U4.3 | length 280.4
  Top Layer w0.5: R4.2@74.93,73.66 R4.2@75.184,74.041 ; R4.2 76.764,74.986 v1(76.764,78.811) v1@76.962,78.613 ; R4.2@75.184,74.156 ccw(c75.184,75.967) 76.464,74.686 ccw(c77.745,73.406) R4.2@75.934,73.406 ; v1@76.41,78.457 cw(c75.557,77.604) 76.764,77.604 cw(c77.971,77.604) v1@77.118,78.457 ; v1@90.152,68.308 cw(c89.495,67.651) 90.424,67.651 cw(c91.353,67.651) v1@90.696,68.308 ; v1(90.424,68.58) 90.424,53.848 v1(92.964,51.308) ; v1@92.579,51.308 ccw(c91.65,51.308) 92.307,51.965 ccw(c92.964,52.622) v1@92.964,51.693 ; U3.31@115.408,71.994 ccw(c114.891,72.771) 115.824,72.771 ; U3.31 115.824,72.771 ; U3.31@116.24,71.994 cw(c116.757,72.771) 115.824,72.771 ; 9014.3@119.711,77.801 cw(c119.284,77.374) 119.888,77.374 cw(c120.492,77.374) 9014.3@120.065,77.801 ; 9014.3 119.888,76.835 115.824,72.771
  Bottom Layer w0.5: U4.3 71.628,65.532 R1.3 72.39,73.406 ; U4.3@67.564,61.968 ccw(c67.564,63.175) 68.418,62.322 ccw(c69.271,61.468) U4.3@68.064,61.468 ; R1.3@71.098,73.638 cw(c69.817,72.357) 71.628,72.357 cw(c73.439,72.357) R1.3@72.158,73.638 ; R1.3@71.451,73.991 ccw(c72.864,75.404) 72.864,73.406 ; R1.3@71.805,74.345 ccw(c74.071,76.611) 74.071,73.406 ; R1.3@71.941,73.486 cw(c72.108,73.124) 72.39,73.406 ; R1.3@72.158,74.698 ccw(c75.278,77.818) R4.2@75.278,73.406 ; R1.3@72.31,73.855 ccw(c72.672,73.688) 72.39,73.406 ; R4.2@74.654,72.876 ccw(c73.373,71.595) 73.373,73.406 ccw(c73.373,75.217) R4.2@74.654,73.936 ; R4.2@75.184,72.656 cw(c75.184,70.845) 76.464,72.126 cw(c77.745,73.406) R4.2@75.934,73.406 ; R4.2 77.216,71.374 R3.2 79.756,69.342 R2.2 U2.8 ; R4.2@75.576,73.014 ccw(c77.724,75.161) R3.2@77.724,72.124 ; R4.2@75.714,72.876 cw(c76.995,71.595) 76.995,73.406 cw(c76.995,75.217) R4.2@75.714,73.936 ; Dis1.2@76.234,82.898 cw(c74.953,81.617) 76.764,81.617 cw(c78.575,81.617) Dis1.2@77.294,82.898 ; v1@76.41,79.165 ccw(c75.557,80.018) 76.764,80.018 ccw(c77.971,80.018) v1@77.118,79.165 ; 76.43,72.16 ccw(c77.724,73.454) R3.2@77.724,71.624 ; v1(76.764,78.811) Dis1.2 ; 76.803,71.787 cw(c76.39,71.374) R3.2@76.974,71.374 ; R3.2@77.724,70.624 cw(c77.724,68.813) 79.004,70.094 cw(c80.285,71.374) R3.2@78.474,71.374 ; R3.2@78.116,70.982 ccw(c80.264,73.129) R2.2@80.264,70.092 ; 78.97,70.128 ccw(c80.264,71.422) R2.2@80.264,69.592 ; 79.343,69.755 cw(c78.93,69.342) R2.2@79.514,69.342 ; U2.8@79.734,67.078 ccw(c78.453,68.359) 80.264,68.359 ccw(c82.075,68.359) U2.8@80.794,67.078 ; R2.2@79.734,68.812 cw(c78.453,67.531) 80.264,67.531 cw(c82.075,67.531) R2.2@80.794,68.812 ; v1(90.424,68.58) U3.40 88.9,75.184 79.756,75.184 77.978,73.406 72.39,73.406 ; v1@90.424,68.965 ccw(c90.424,69.894) 91.081,69.237 ccw(c91.738,68.58) v1@90.809,68.58 ; 91.257,69.413 cw(c92.964,67.706) U3.40@92.964,70.12 ; 91.257,72.827 ccw(c92.964,74.534) U3.40@92.964,72.12 ; 91.86,70.016 ccw(c91.007,70.87) U3.40@92.214,70.87 ; 91.86,72.224 cw(c91.007,71.37) U3.40@92.214,71.37 ; 92.11,70.266 cw(c92.964,69.413) U3.40@92.964,70.62 ; 92.11,71.974 ccw(c92.964,72.827) U3.40@92.964,71.62 ; U3.40@92.434,71.9 ccw(c91.153,73.181) 92.964,73.181 ccw(c94.775,73.181) U3.40@93.494,71.9 ; 92.434,74.146 cw(c91.153,72.865) 92.964,72.865 cw(c94.775,72.865) 93.494,74.146 ; v1(92.964,51.308) C3.1 103.037,48.228 151.511,48.228 C2.2 156.464,51.308 159.004,53.848 U1.2 ; 92.964,74.676 92.964,69.698 ; v1@93.236,51.036 cw(c93.893,50.379) 93.893,51.308 cw(c93.893,52.237) v1@93.236,51.58 ; C3.1@100.094,50.778 ccw(c98.813,49.497) 98.813,51.308 ccw(c98.813,53.119) C3.1@100.094,51.838 ; C3.1@100.534,50.563 cw(c100.315,48.766) 101.741,49.883 cw(c103.166,50.999) C3.1@101.369,51.218 ; U3.31@115.51,70.189 cw(c115.283,69.698) 115.824,69.698 ; U3.31 115.824,69.698 ; U3.31@116.138,70.189 ccw(c116.365,69.698) 115.824,69.698 ; C2.2@153.179,51.218 cw(c151.382,50.999) 152.807,49.883 cw(c154.233,48.766) C2.2@154.014,50.563 ; C2.2@154.454,50.778 cw(c155.735,49.497) 155.735,51.308 cw(c155.735,53.119) C2.2@154.454,51.838 ; U1.2@158.474,55.858 cw(c157.193,54.577) 159.004,54.577 cw(c160.815,54.577) U1.2@159.534,55.858 ; 92.964,69.698 ccw(c92.423,69.698) 92.65,70.189 cw(c92.423,69.698) 92.964,69.698 ; 92.964,69.698 cw(c93.505,69.698) 93.278,70.189 ccw(c93.505,69.698) 92.964,69.698 ; 92.964,69.698 93.472,69.19 115.316,69.19 115.824,69.698
VEE: Dis1.3 R1.1 | length 23.2
  Bottom Layer w0.5: R1.1 72.644,79.248 75.184,76.708 78.486,76.708 79.304,77.526 Dis1.3 ; R1.1@69.618,78.718 cw(c70.899,77.437) 70.899,79.248 cw(c70.899,81.059) R1.1@69.618,79.778 ; Dis1.3@78.774,82.898 cw(c77.493,81.617) 79.304,81.617 cw(c81.115,81.617) Dis1.3@79.834,82.898
pads on no net: U3.5 U3.6 U3.7 U3.8 U3.12 U3.13 U3.14 U3.15 U3.16 U3.17 U3.21 U3.29 U3.30

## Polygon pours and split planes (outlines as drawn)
GND on Bottom Layer (solid, remove dead copper): 63.627,86.614 63.627,45.72 165.354,45.72 165.354,87.503 63.373,87.503 63.373,85.725
GND on Bottom Layer (solid, remove dead copper, shelved): 50.165,103.251 50.165,64.77 149.86,64.77 149.86,103.251

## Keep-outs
Keep-Out Layer:
  lines w0.254: 64.224,47.179 164.224,47.179 164.224,85.979 64.224,85.979 64.224,47.179

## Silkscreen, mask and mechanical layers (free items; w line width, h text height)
Mechanical 1:
  lines w0.127: 50.588,95.495 53.128,95.495 ; 50.588,129.495 53.128,129.495 ; 51.858,94.225 51.858,96.765 ; 51.858,128.225 51.858,130.765 ; 58.088,129.495 60.628,129.495 ; 59.358,128.225 59.358,130.765 ; 145.588,95.495 148.128,95.495 ; 145.588,129.495 148.128,129.495 ; 146.858,94.225 146.858,96.765 ; 146.858,128.225 146.858,130.765 ; 49.358,93.095 49.358,131.895 149.358,131.895 149.358,93.095 49.358,93.095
